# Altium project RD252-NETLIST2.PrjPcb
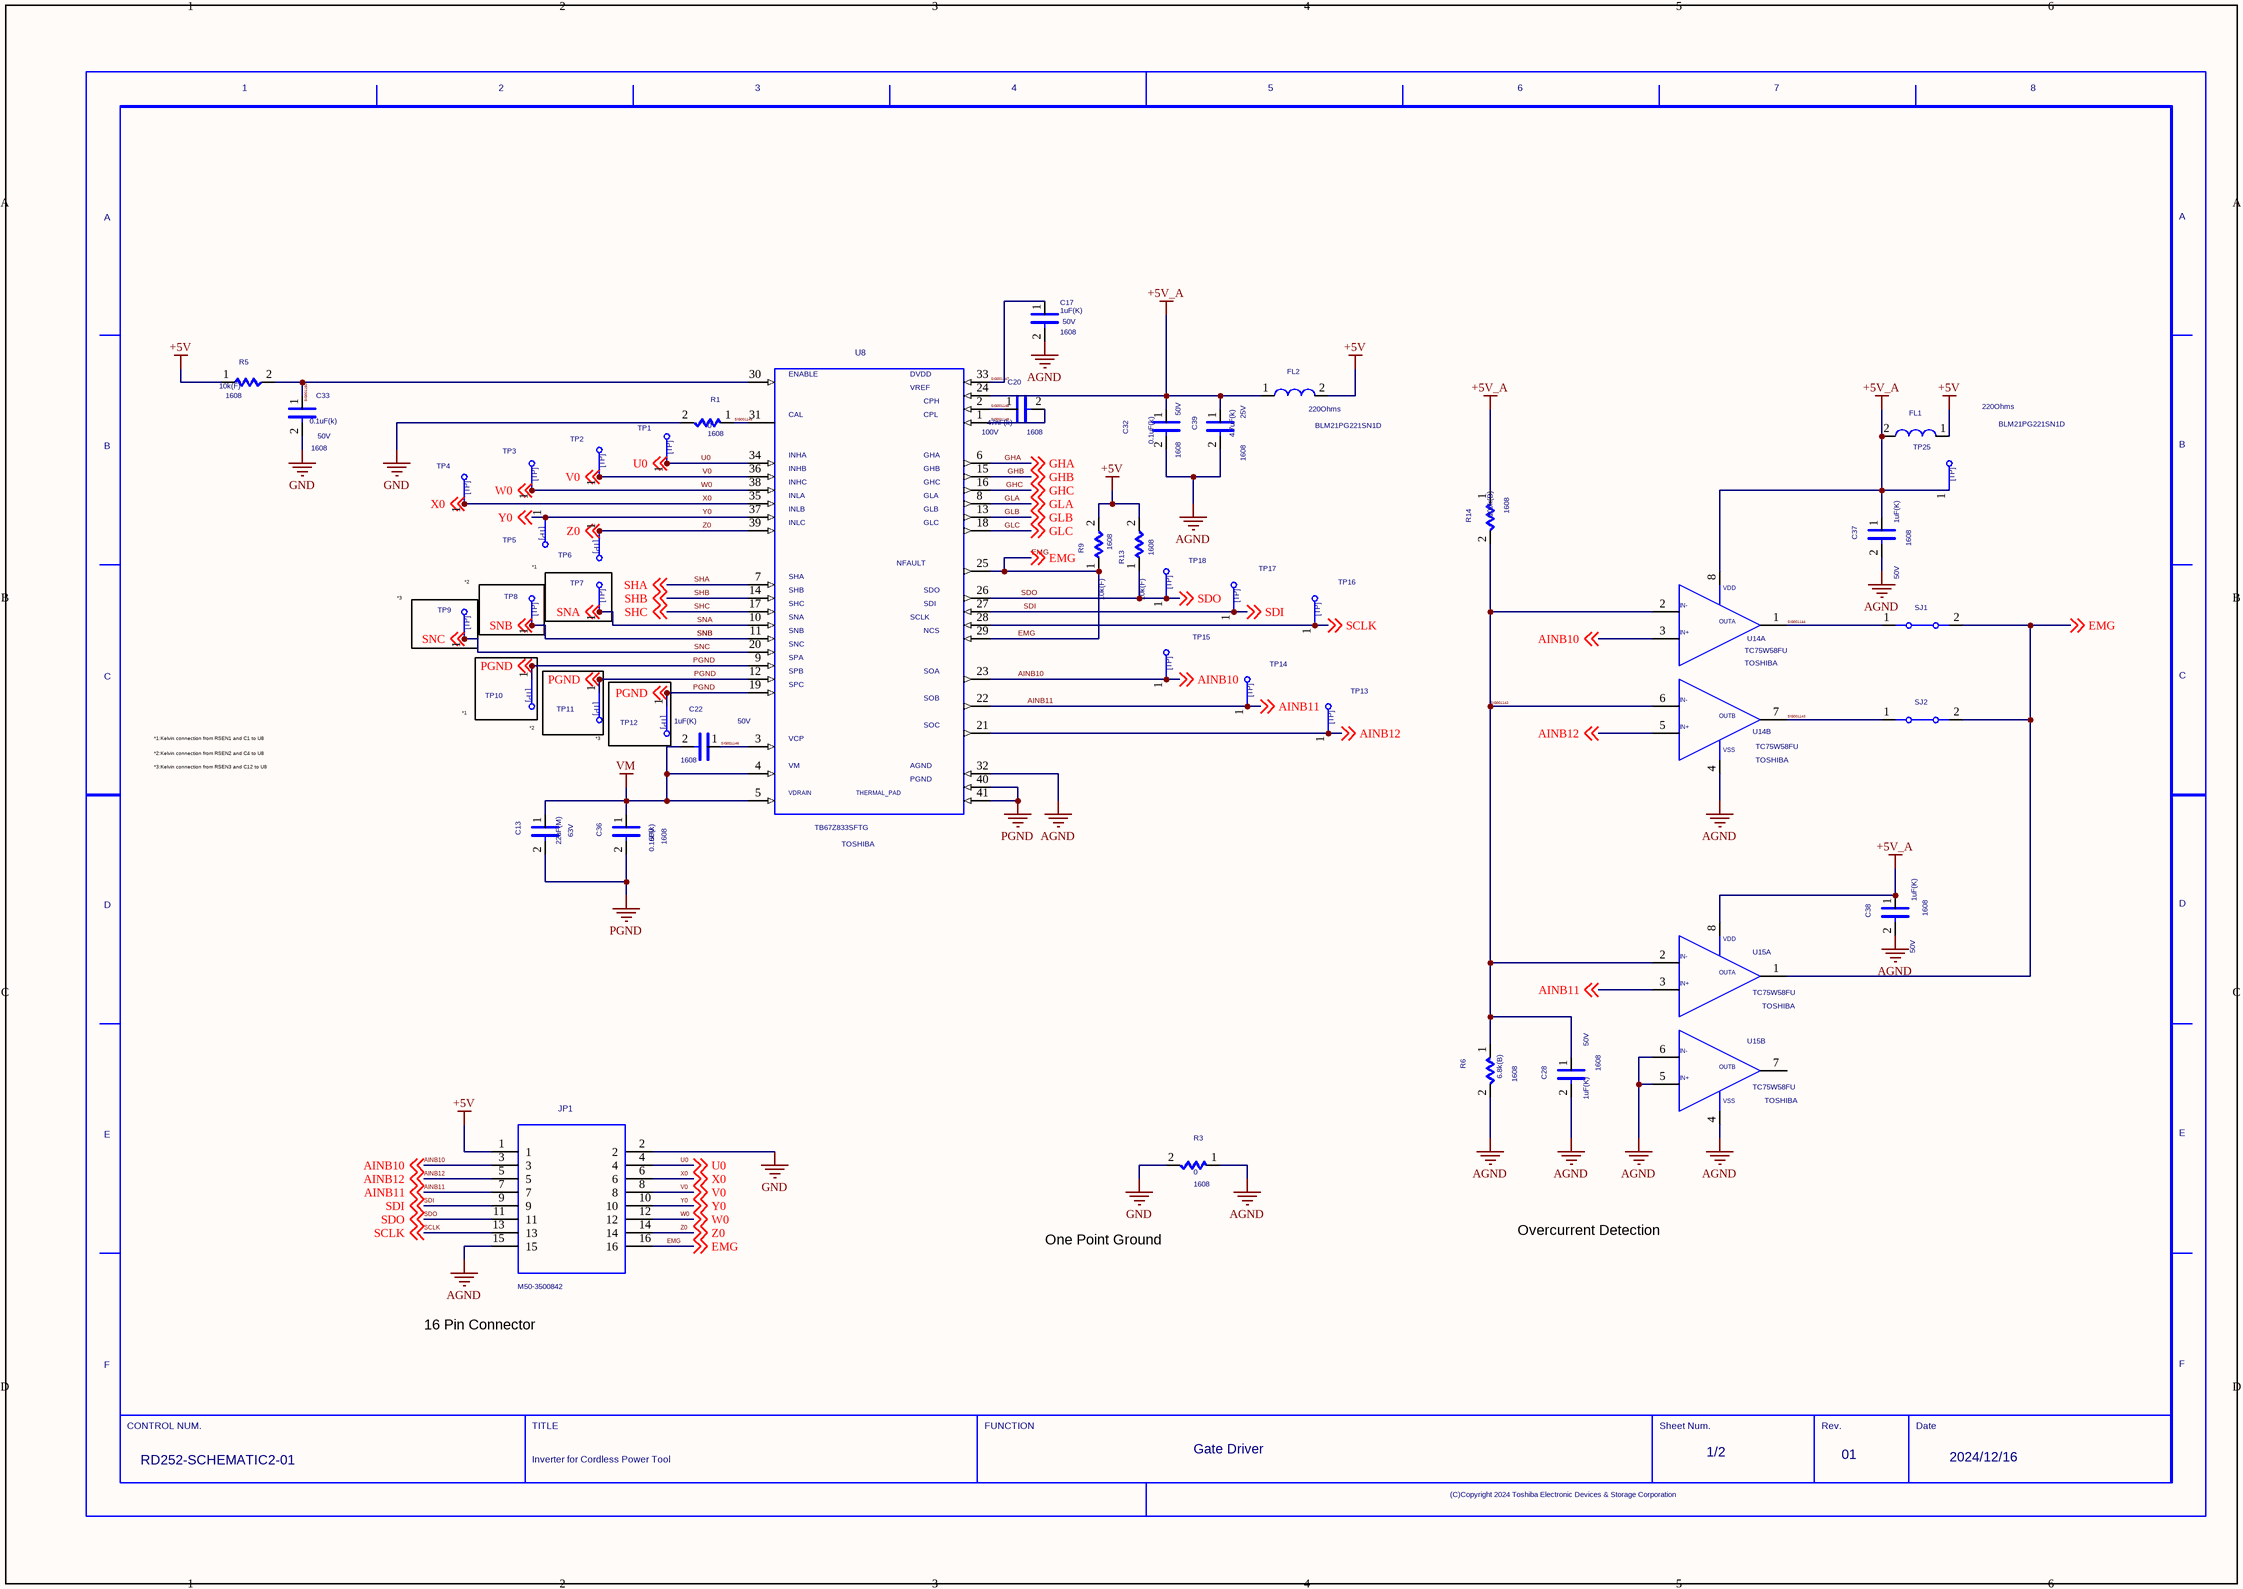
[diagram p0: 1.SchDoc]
2 sheets, 83 parts. Net scope: global (net labels, ports and power ports of the same name join across sheets).
Sheets:
  1.SchDoc
  2.SchDoc

## Sheet 1.SchDoc
size 420 x 297 mm

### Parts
(Parts that share a designator on the sheet are numbered #1, #2 ... from top to bottom, then left to right.)
C13  VAL2: 63V  VAL1: 22uF(M)  (hidden comment: C)
C17  SIZECODESMD: 1608  VAL2: 50V  VAL1: 1uF(K)  (hidden comment: C)
C20  SIZECODESMD: 1608  VAL2: 100V  VAL1: 47nF(k)  (hidden comment: C)
C22  VAL2: 50V  SIZECODESMD: 1608  VAL1: 1uF(K)  (hidden comment: C)
C28  SIZECODESMD: 1608  VAL2: 50V  VAL1: 1uF(K)  (hidden comment: C)
C32  SIZECODESMD: 1608  VAL2: 50V  VAL1: 0.1uF(k)  (hidden comment: C)
C33  SIZECODESMD: 1608  VAL2: 50V  VAL1: 0.1uF(k)  (hidden comment: C)
C36  SIZECODESMD: 1608  VAL2: 50V  VAL1: 0.1uF(k)  (hidden comment: C)
C37  SIZECODESMD: 1608  VAL2: 50V  VAL1: 1uF(K)  (hidden comment: C)
C38  SIZECODESMD: 1608  VAL2: 50V  VAL1: 1uF(K)  (hidden comment: C)
C39  SIZECODESMD: 1608  VAL2: 25V  VAL1: 4.7uF(k)  (hidden comment: C)
FL1  VAL1: 220Ohms  VAL3: BLM21PG221SN1D  (hidden comment: L)
FL2  VAL1: 220Ohms  VAL3: BLM21PG221SN1D  (hidden comment: L)
JP1  VAL3: M50-3500842  [IDC16_1_27MM]  (hidden comment: CONN_16PINJ)
R1  SIZECODESMD: 1608  VAL1: 0  (hidden comment: R)
R3  SIZECODESMD: 1608  VAL1: 0  (hidden comment: R)
R5  SIZECODESMD: 1608  VAL1: 10k(F)  (hidden comment: R)
R6  SIZECODESMD: 1608  VAL1: 6.8k(B)  (hidden comment: R)
R9  SIZECODESMD: 1608  VAL1: 10k(F)  (hidden comment: R)
R13  SIZECODESMD: 1608  VAL1: 10k(F)  (hidden comment: R)
R14  SIZECODESMD: 1608  VAL1: 100k(B)  (hidden comment: R)
SJ1  JP  (value not drawn)
SJ2  JP  (value not drawn)
TP1  TP  (value not drawn)
TP2  TP  (value not drawn)
TP3  TP  (value not drawn)
TP4  TP  (value not drawn)
TP5  TP  (value not drawn)
TP6  TP  (value not drawn)
TP7  TP  (value not drawn)
TP8  TP  (value not drawn)
TP9  TP  (value not drawn)
TP10  TP  (value not drawn)
TP11  TP  (value not drawn)
TP12  TP  (value not drawn)
TP13  TP  (value not drawn)
TP14  TP  (value not drawn)
TP15  TP  (value not drawn)
TP16  TP  (value not drawn)
TP17  TP  (value not drawn)
TP18  TP  (value not drawn)
TP25  TP  (value not drawn)
U8  USERCOMPTEXT3: TOSHIBA  VAL3: TB67Z833SFTG  (hidden comment: DRV8323S)
U14  USERCOMPTEXT3: TOSHIBA  VAL3: TC75W58FU  (hidden comment: NA)  (parts A,B of 2)
U15  USERCOMPTEXT3: TOSHIBA  VAL3: TC75W58FU  (hidden comment: NA)  (parts A,B of 2)
U?#1  DATE: 2024/12/16  FUNCTION: Gate Driver  TITLE: Inverter for Cordless Power Tool  REVISION: 01  SHEETNUMBER: 1/2  DRAWINGNUMBER: RD252-SCHEMATIC2-01  (hidden comment: WAKU_DEF100)

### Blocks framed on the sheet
*2: TP9
*1: TP8

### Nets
+5V: FL1.1 FL2.2 JP1.1 R5.1 R9.2 R13.2
+5V_A: C32.1 C37.1 C38.1 C39.1 FL1.2 FL2.1 R14.1 TP25.1 U8.24 U14.8 U15.8
AGND: C17.2 C28.2 C32.2 C37.2 C38.2 C39.2 JP1.15 R3.1 R6.2 U8.32 U14.4 U15.4 U15.5 U15.6
GND: C33.2 JP1.2 R1.2 R3.2
PGND: C13.2 C36.2 TP10.1 TP11.1 TP12.1 U8.9 U8.12 U8.19 U8.40 U8.41 ; off-sheet PGND
VM: C13.1 C22.2 C36.1 U8.4 U8.5
AINB10: JP1.3 TP15.1 U8.23 U14.3 ; off-sheet AINB10
AINB11: JP1.7 TP14.1 U8.22 U15.3 ; off-sheet AINB11
AINB12: JP1.5 TP13.1 U8.21 U14.5 ; off-sheet AINB12
EMG: JP1.16 R9.1 SJ1.2 SJ2.2 U8.25 U8.29 U15.1 ; off-sheet EMG
GHA: U8.6 ; off-sheet GHA
GHB: U8.15 ; off-sheet GHB
GHC: U8.16 ; off-sheet GHC
GLA: U8.8 ; off-sheet GLA
GLB: U8.13 ; off-sheet GLB
GLC: U8.18 ; off-sheet GLC
SCLK: JP1.13 TP16.1 U8.28 ; off-sheet SCLK
SDI: JP1.9 TP17.1 U8.27 ; off-sheet SDI
SDO: JP1.11 R13.1 TP18.1 U8.26 ; off-sheet SDO
SHA: U8.7 ; off-sheet SHA
SHB: U8.14 ; off-sheet SHB
SHC: U8.17 ; off-sheet SHC
SIG001142: C28.1 R6.1 R14.2 U14.2 U14.6 U15.2
SIG001143: SJ2.1 U14.7
SIG001144: SJ1.1 U14.1
SIG001145: R1.1 U8.31
SIG001146: C22.1 U8.3
SIG001147: C17.1 U8.33
SIG001148: C20.1 U8.2
SIG001149: C20.2 U8.1
SIG001150: C33.1 R5.2 U8.30
SNA: TP7.1 U8.10 ; off-sheet SNA
SNB: TP8.1 U8.11 ; off-sheet SNB
SNC: TP9.1 U8.20 ; off-sheet SNC
U0: JP1.4 TP1.1 U8.34 ; off-sheet U0
V0: JP1.8 TP2.1 U8.36 ; off-sheet V0
W0: JP1.12 TP3.1 U8.38 ; off-sheet W0
X0: JP1.6 TP4.1 U8.35 ; off-sheet X0
Y0: JP1.10 TP5.1 U8.37 ; off-sheet Y0
Z0: JP1.14 TP6.1 U8.39 ; off-sheet Z0

Not connected (* = marked no-connect by the designer): U15 7

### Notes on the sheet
- *3
- *1
- *2
- *1:Kelvin connection from RSEN1 and C1 to U8
- *2:Kelvin connection from RSEN2 and C4 to U8
- *3:Kelvin connection from RSEN3 and C12 to U8
- (near TP11) *3
- One Point Ground
- Overcurrent Detection
- 16 Pin Connector

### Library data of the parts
C13 C17 C20 C22 C28 C32 C33 C36-C39 = C: TIME: 17:22:43; UPDATEUSER: t5459927; SAVECOUNT: 1; ORIGINALSYMBOLORIGIN: (-2540,5080)
FL1 FL2 = L: SAVECOUNT: 24; SAVEAREA0: -14227,-538,38802,29317; TIME: 11:19:06; UPDATEUSER: sptcae09; UPDATETIME: 15:04:42; COMP: 750315038; OriginalSymbolOrigin: (2540,5080)
JP1 = CONN_16PINJ_JP1: TIME: 10:49:14; UPDATEUSER: sptcae09; SAVECOUNT: 2; MP: TSM-108-01-L-DV; DEVICENAME: J; ORIGIN: Altium; MF: Samtec; GATENAME_1: A; OriginalSymbolOrigin: (0,0); INSTANCENAME: INS1151
R1 R3 = R: TIME: 17:22:43; UPDATEUSER: t5459927; SAVECOUNT: 1; ORIGINALSYMBOLORIGIN: (2540,2540); VAL2: 1A
R5 R9 R13 = R: TIME: 17:22:43; UPDATEUSER: t5459927; SAVECOUNT: 1; ORIGINALSYMBOLORIGIN: (2540,2540); VAL2: 330mW
R6 R14 = R: TIME: 17:22:43; UPDATEUSER: t5459927; SAVECOUNT: 1; ORIGINALSYMBOLORIGIN: (2540,2540); VAL2: 200mW
SJ1 SJ2 = JP: OriginalSymbolOrigin: (2540,5080); VAL3: Solder_Jumper; COMP: SJ; SAVECOUNT: 0
TP1-TP18 TP25 = TP: TIME: 16:12:21; UPDATEUSER: fukuda-y; UPDATETIME: 16:18:11; SAVECOUNT: 2; SAVEAREA0: -242,-92,12810,7836; OriginalSymbolOrigin: (0,7620)
U8 = TB67Z833SFTG_U8: TIME: 10:49:18; UPDATEUSER: t5459927; UPDATETIME: 18:24:11; SAVECOUNT: 5; MP: DRV8323SRTAT; ORIGIN: Altium; MF: Texas Instruments; GATENAME_1: G$1; OriginalSymbolOrigin: (0,0)
U14 U15 = TC75W58FU_1: TIME: 10:49:18; UPDATEUSER: t5459927; UPDATETIME: 18:58:17; SAVECOUNT: 8; GATENAME_1: G$1; SYMBOLNAME_1: TPH1R204PB; ORIGIN: Altium; OriginalSymbolOrigin: (0,0); CaptureCellPackProp: TC75W58FU_1A
U?#1 = WAKU_DEF100_1: TIME: 14:30:25; UPDATEUSER: cae; UPDATETIME: 17:20:18; SAVECOUNT: 3; PLOTTIME: HH:MM; SAVEAREA0: -63393,-16950,474261,314592; ORIGINALSYMBOLORIGIN: (0,0); SHTSAVECOUNT: 90

## Sheet 2.SchDoc
size 420 x 297 mm
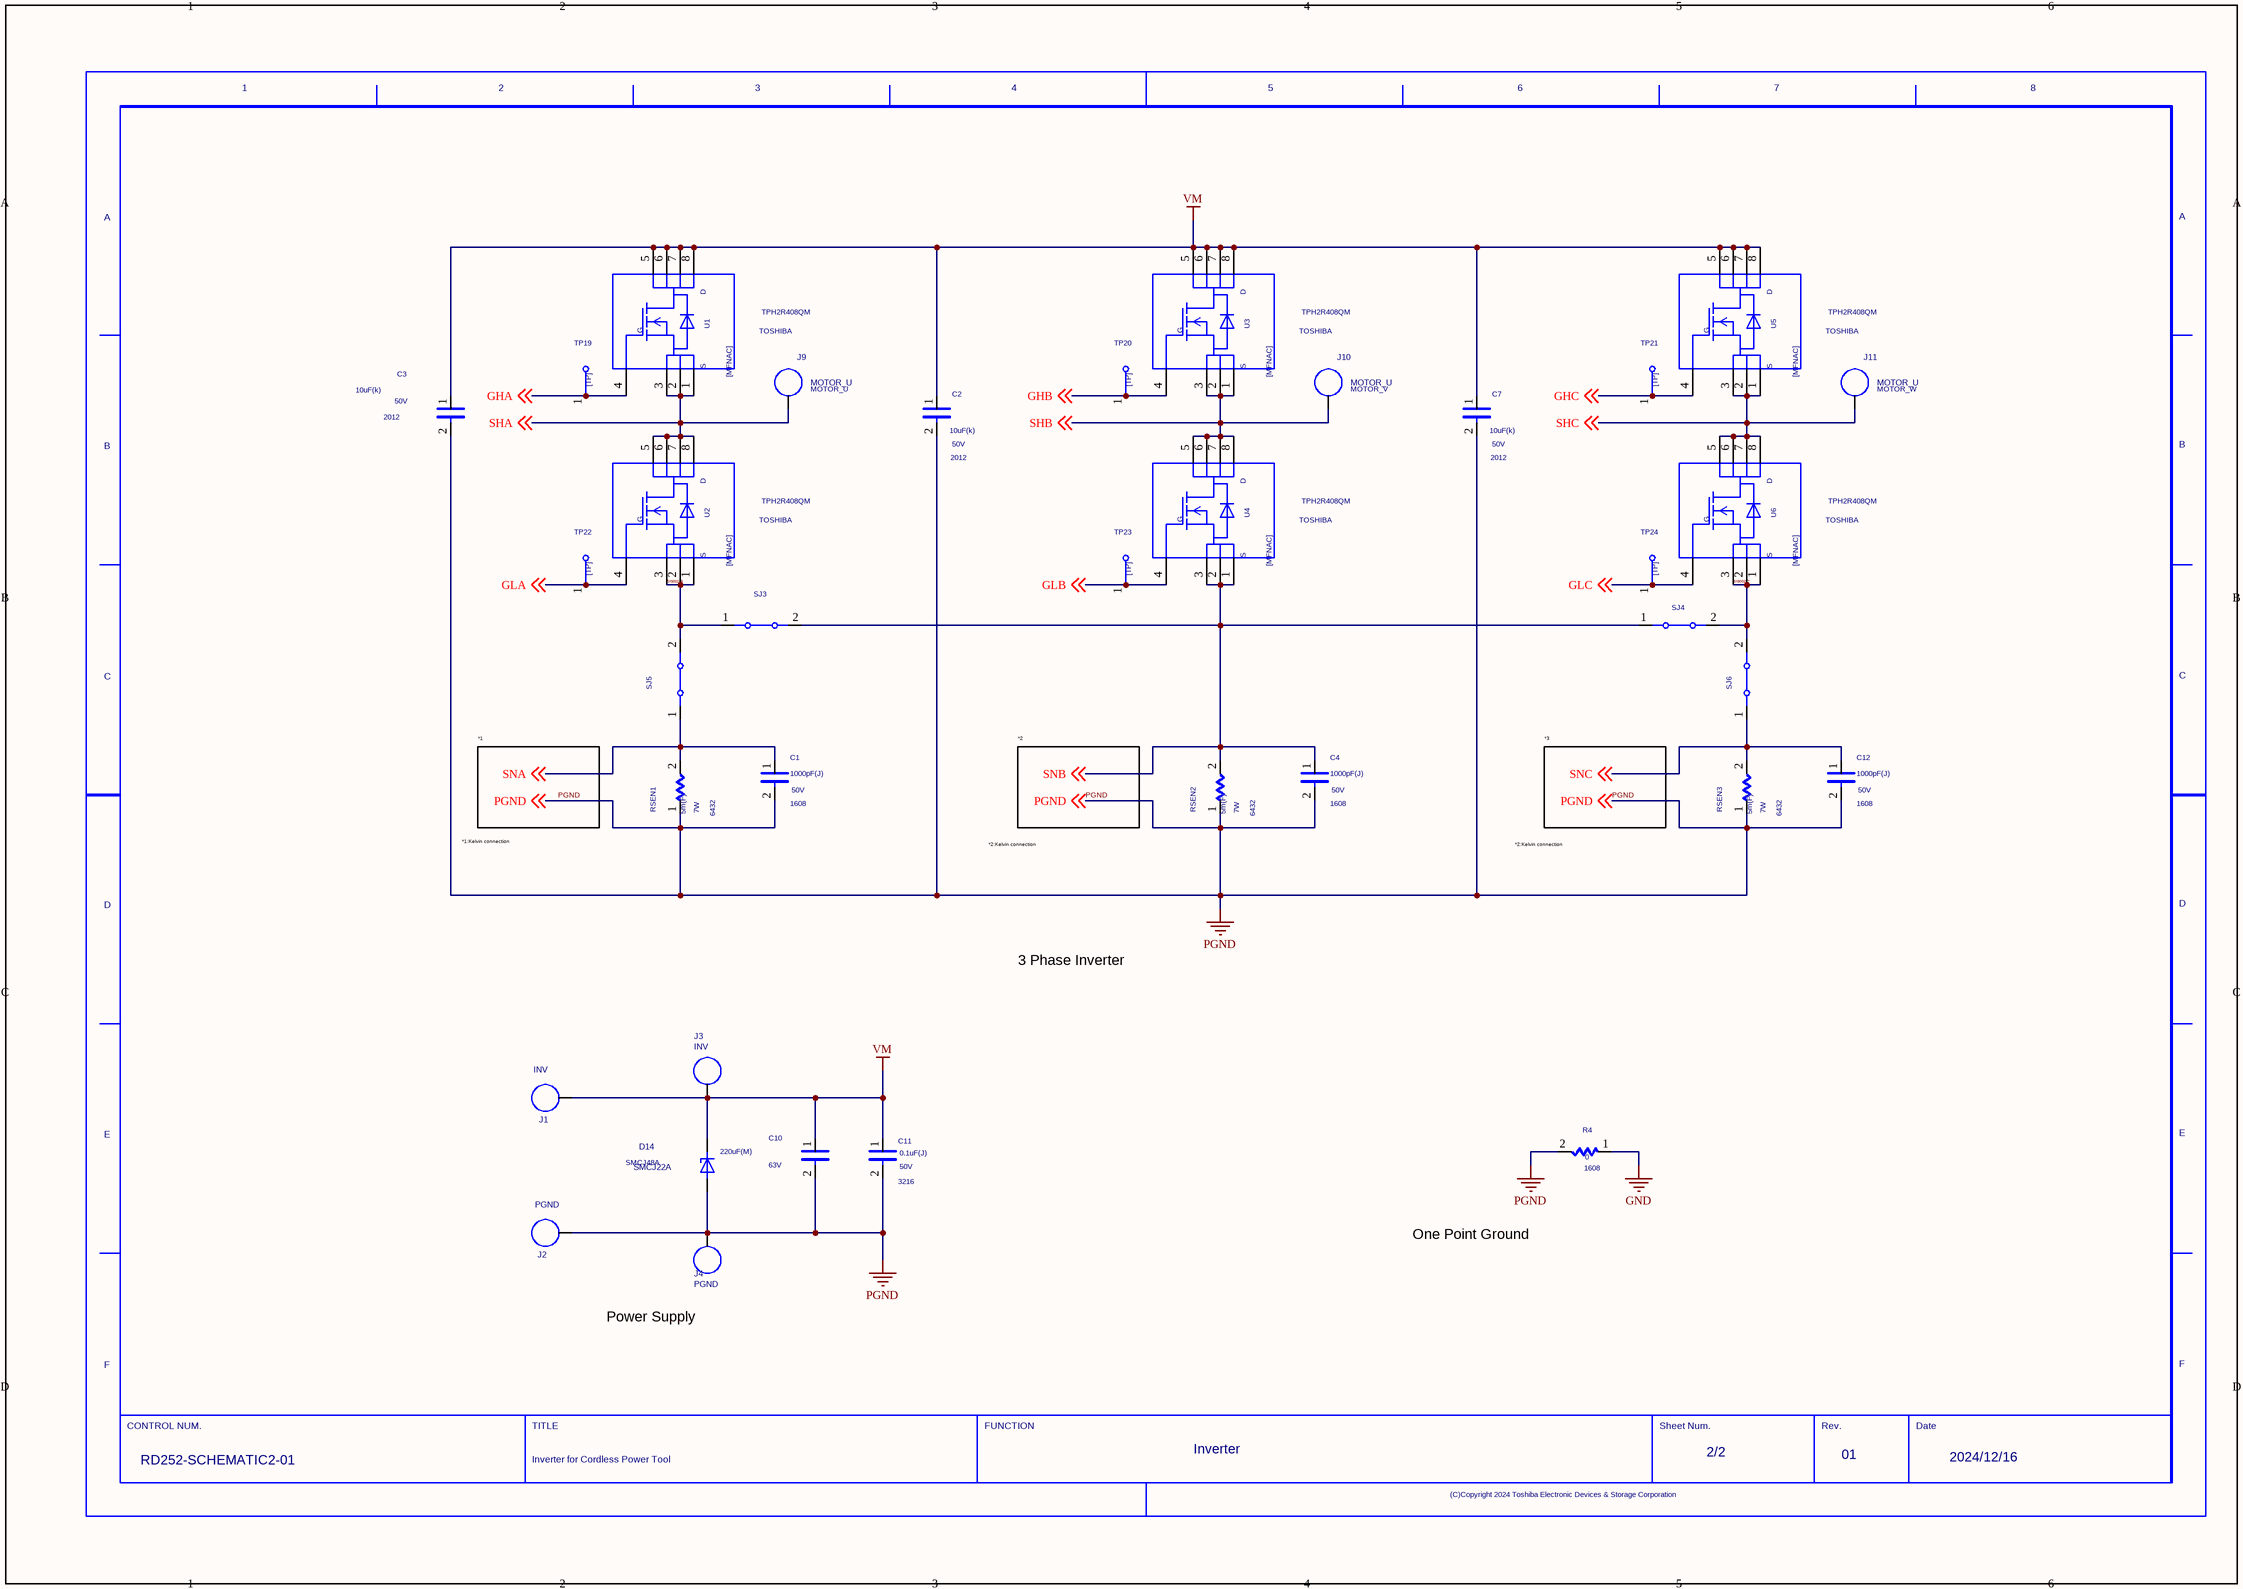
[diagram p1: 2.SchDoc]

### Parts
(Parts that share a designator on the sheet are numbered #1, #2 ... from top to bottom, then left to right.)
C1  SIZECODESMD: 1608  VAL2: 50V  VAL1: 1000pF(J)  (hidden comment: C)
C2  SIZECODESMD: 2012  VAL2: 50V  VAL1: 10uF(k)  (hidden comment: C)
C3  SIZECODESMD: 2012  VAL2: 50V  VAL1: 10uF(k)  (hidden comment: C)
C4  SIZECODESMD: 1608  VAL2: 50V  VAL1: 1000pF(J)  (hidden comment: C)
C7  SIZECODESMD: 2012  VAL2: 50V  VAL1: 10uF(k)  (hidden comment: C)
C10  VAL2: 63V  VAL1: 220uF(M)  (hidden comment: C)
C11  SIZECODESMD: 3216  VAL2: 50V  VAL1: 0.1uF(J)  (hidden comment: C)
C12  SIZECODESMD: 1608  VAL2: 50V  VAL1: 1000pF(J)  (hidden comment: C)
D14  SMCJ22A  VAL3: SMCJ48A  [DSMC]
J1  INV  [TP_SM]
J2  PGND  [TP_SM]
J3  INV  [TP_SM]
J4  PGND  [TP_SM]
J9  MOTOR_U  [TP_SM]
J10  MOTOR_U  VAL3: MOTOR_V  [TP_SM]
J11  MOTOR_U  VAL3: MOTOR_W  [TP_SM]
R4  SIZECODESMD: 1608  VAL1: 0  (hidden comment: R)
RSEN1  SIZECODESMD: 6432  VAL2: 7W  VAL1: 5m(F)  (hidden comment: R)
RSEN2  SIZECODESMD: 6432  VAL2: 7W  VAL1: 5m(F)  (hidden comment: R)
RSEN3  SIZECODESMD: 6432  VAL2: 7W  VAL1: 5m(F)  (hidden comment: R)
SJ3  JP  (value not drawn)
SJ4  JP  (value not drawn)
SJ5  JP  (value not drawn)
SJ6  JP  (value not drawn)
TP19  TP  (value not drawn)
TP20  TP  (value not drawn)
TP21  TP  (value not drawn)
TP22  TP  (value not drawn)
TP23  TP  (value not drawn)
TP24  TP  (value not drawn)
U1  USERCOMPTEXT3: TOSHIBA  VAL3: TPH2R408QM  (hidden comment: MFNAC)
U2  USERCOMPTEXT3: TOSHIBA  VAL3: TPH2R408QM  (hidden comment: MFNAC)
U3  USERCOMPTEXT3: TOSHIBA  VAL3: TPH2R408QM  (hidden comment: MFNAC)
U4  USERCOMPTEXT3: TOSHIBA  VAL3: TPH2R408QM  (hidden comment: MFNAC)
U5  USERCOMPTEXT3: TOSHIBA  VAL3: TPH2R408QM  (hidden comment: MFNAC)
U6  USERCOMPTEXT3: TOSHIBA  VAL3: TPH2R408QM  (hidden comment: MFNAC)
U?#2  DATE: 2024/12/16  FUNCTION: Inverter  TITLE: Inverter for Cordless Power Tool  REVISION: 01  SHEETNUMBER: 2/2  DRAWINGNUMBER: RD252-SCHEMATIC2-01  (hidden comment: WAKU_DEF100)

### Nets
GND: R4.1
PGND: C1.2 C2.2 C3.2 C4.2 C7.2 C10.2 C11.2 C12.2 D14.A J2.1 J4.1 R4.2 RSEN1.1 RSEN2.1 RSEN3.1 ; off-sheet PGND
VM: C2.1 C3.1 C7.1 C10.1 C11.1 D14.C J1.1 J3.1 U1.5 U1.6 U1.7 U1.8 U3.5 U3.6 U3.7 U3.8 U5.5 U5.6 U5.7 U5.8
GHA: TP19.1 U1.4 ; off-sheet GHA
GHB: TP20.1 U3.4 ; off-sheet GHB
GHC: TP21.1 U5.4 ; off-sheet GHC
GLA: TP22.1 U2.4 ; off-sheet GLA
GLB: TP23.1 U4.4 ; off-sheet GLB
GLC: TP24.1 U6.4 ; off-sheet GLC
SHA: J9.1 U1.1 U1.2 U1.3 U2.5 U2.6 U2.7 U2.8 ; off-sheet SHA
SHB: J10.1 U3.1 U3.2 U3.3 U4.5 U4.6 U4.7 U4.8 ; off-sheet SHB
SHC: J11.1 U5.1 U5.2 U5.3 U6.5 U6.6 U6.7 U6.8 ; off-sheet SHC
SIG00255: SJ3.1 SJ5.2 U2.1 U2.2 U2.3
SIG00257: SJ4.2 SJ6.2 U6.1 U6.2 U6.3
SNA: C1.1 RSEN1.2 SJ5.1 ; off-sheet SNA
SNB: C4.1 RSEN2.2 SJ3.2 SJ4.1 U4.1 U4.2 U4.3 ; off-sheet SNB
SNC: C12.1 RSEN3.2 SJ6.1 ; off-sheet SNC

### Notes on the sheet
- *1
- *2
- *3
- *1:Kelvin connection
  from RSEN1 and C1 to U8
- *2:Kelvin connection
  from RSEN2 and C4 to U8
- *2:Kelvin connection
  from RSEN3 and C12 to U8
- 3 Phase Inverter
- One Point Ground
- Power Supply

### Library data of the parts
C1-C4 C7 C10-C12 = C: as C13 on sheet 1
D14 = SMCJ22A_D14: TIME: 10:49:12; UPDATEUSER: sptcae09; UPDATETIME: 10:49:13; SAVECOUNT: 2; ORIGIN: Altium; MF: Littelfuse; GATENAME_1: G$1; OriginalSymbolOrigin: (0,1270); INSTANCENAME: INS1233
J1 = 1X1HEADER_J1: TIME: 10:49:17; UPDATEUSER: sptcae09; UPDATETIME: 10:49:18; SAVECOUNT: 2; GATENAME_1: G$1; ORIGIN: Altium; OriginalSymbolOrigin: (-5080,2540); VAL3: Through Hole; INSTANCENAME: INS1187
J2 = 1X1HEADER_J2: TIME: 10:49:18; UPDATEUSER: sptcae09; UPDATETIME: 10:49:19; SAVECOUNT: 2; GATENAME_1: G$1; ORIGIN: Altium; OriginalSymbolOrigin: (-5080,2540); VAL3: Through Hole; INSTANCENAME: INS1195
J3 = 1X1HEADER_J3: TIME: 10:49:12; UPDATEUSER: sptcae09; SAVECOUNT: 2; GATENAME_1: G$1; ORIGIN: Altium; OriginalSymbolOrigin: (-2540,5080); VAL3: Through Hole; INSTANCENAME: INS1429
J4 = 1X1HEADER_J4: TIME: 10:49:13; UPDATEUSER: sptcae09; SAVECOUNT: 2; GATENAME_1: G$1; ORIGIN: Altium; OriginalSymbolOrigin: (-2540,0); VAL3: Through Hole; INSTANCENAME: INS1437
J9-J11 = 1X1HEADER_J9: TIME: 10:49:11; UPDATEUSER: sptcae09; UPDATETIME: 10:49:12; SAVECOUNT: 2; GATENAME_1: G$1; ORIGIN: Altium; OriginalSymbolOrigin: (-2540,5080); USEWITHLAYOUT: YES; INSTANCENAME: INS1015
R4 = R: as R1 on sheet 1
RSEN1-RSEN3 = R: TIME: 17:22:43; UPDATEUSER: t5459927; SAVECOUNT: 1; ORIGINALSYMBOLORIGIN: (2540,2540)
SJ3-SJ6 = JP: as SJ1 on sheet 1
TP19-TP24 = TP: as TP1 on sheet 1
U1-U6 = MFNAC: TIME: 18:29:30; UPDATEUSER: 19990028; UPDATETIME: 14:45:16; SAVECOUNT: 26; SAVEAREA0: -10143,-336,37609,28718; OriginalSymbolOrigin: (5080,25400)
U?#2 = WAKU_DEF100_1: TIME: 14:30:25; UPDATEUSER: sptcae09; UPDATETIME: 10:36:43; SAVECOUNT: 3; PLOTTIME: HH:MM; SAVEAREA0: -63393,-16950,474261,314592; ORIGINALSYMBOLORIGIN: (0,0); SHTSAVECOUNT: 42

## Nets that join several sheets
GND: 1 (C33.2 JP1.2 R1.2 R3.2), 2 (R4.1)
PGND: 1 (10 pins), 2 (15 pins)
VM: 1 (5 pins), 2 (20 pins)
GHA: 1 (U8.6), 2 (TP19.1 U1.4)
GHB: 1 (U8.15), 2 (TP20.1 U3.4)
GHC: 1 (U8.16), 2 (TP21.1 U5.4)
GLA: 1 (U8.8), 2 (TP22.1 U2.4)
GLB: 1 (U8.13), 2 (TP23.1 U4.4)
GLC: 1 (U8.18), 2 (TP24.1 U6.4)
SHA: 1 (U8.7), 2 (8 pins)
SHB: 1 (U8.14), 2 (8 pins)
SHC: 1 (U8.17), 2 (8 pins)
SNA: 1 (TP7.1 U8.10), 2 (C1.1 RSEN1.2 SJ5.1)
SNB: 1 (TP8.1 U8.11), 2 (7 pins)
SNC: 1 (TP9.1 U8.20), 2 (C12.1 RSEN3.2 SJ6.1)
